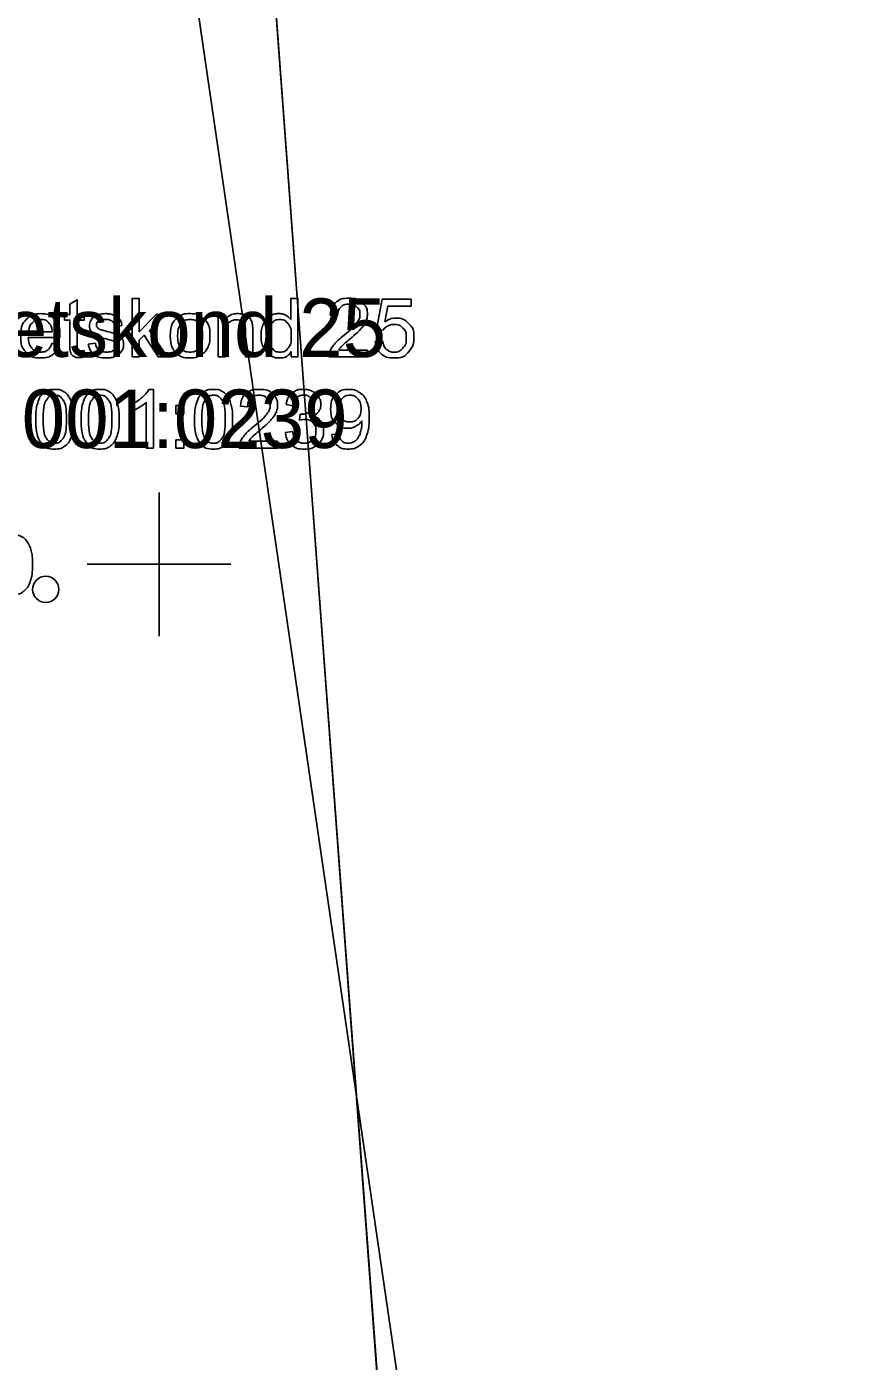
# Model space of a CAD drawing. Extents: x 700746 to 706058, y 6570320 to 6580460.
# Drawn here: x 703387.1 to 703467.1, y 6576222.3 to 6576352.4 of the extents above; entities that cross this region are included whole.
import ezdxf

# ---------------------------------------------------------------- set-up
doc = ezdxf.new("R2010")
doc.units = 0
for name, color, linetype in [('HALJASTUS', 7, 'Continuous'), ('Kaitsevöönd', 7, 'Continuous'), ('kataster', 7, 'Continuous'), ('Plokid', 7, 'Continuous'), ('VORK', 7, 'Continuous'), ('VWX2_MV_PLOKK', 7, 'Continuous')]:
    doc.layers.add(name, color=color, linetype=linetype)

msp = doc.modelspace()

# ---------------------------------------------------------------- linework, layer by layer
at = {"layer": 'HALJASTUS'}
msp.add_circle((703388.95, 6576297.55), 1.28, dxfattribs=at)
at = {"layer": 'Kaitsevöönd'}
msp.add_lwpolyline([(703341.02, 6576780.18), (703353.27, 6576691.8), (703361.05, 6576648.11), (703361.38, 6576646.79), (703378.43, 6576537.56), (703379.92, 6576517.69), (703382.07, 6576503.63), (703404.08, 6576352.03), (703454.73, 6576005.46)], dxfattribs=at)
at = {"layer": 'kataster'}
for points in [[(703391.3, 6576321.42), (703391.3, 6576323.8), (703390.78, 6576323.8), (703390.78, 6576324.34), (703391.3, 6576324.34), (703391.3, 6576325.36), (703392, 6576325.78), (703392, 6576324.34), (703392.7, 6576324.34), (703392.7, 6576323.8), (703392, 6576323.8), (703392, 6576321.38)], [(703397.37, 6576320.21), (703397.37, 6576325.91), (703398.07, 6576325.91), (703398.07, 6576322.66), (703399.73, 6576324.34), (703400.64, 6576324.34), (703399.06, 6576322.8), (703400.8, 6576320.21), (703399.93, 6576320.21), (703398.56, 6576322.32), (703398.07, 6576321.84), (703398.07, 6576320.21), (703397.37, 6576320.21)], [(703412.84, 6576323.86), (703412.84, 6576325.91), (703413.54, 6576325.91), (703413.54, 6576320.21), (703412.89, 6576320.21)], [(703421.86, 6576322.82), (703421.2, 6576322.9), (703421.76, 6576325.83), (703424.59, 6576325.83), (703424.59, 6576325.16), (703422.32, 6576325.16), (703422.01, 6576323.63)], [(703405.78, 6576320.21), (703405.78, 6576324.34), (703406.41, 6576324.34), (703406.41, 6576323.75)], [(703417.41, 6576324.21), (703416.69, 6576324.28)], [(703387.27, 6576322.67), (703389.58, 6576322.67)], [(703396.38, 6576323.27), (703395.7, 6576323.18)], [(703409.14, 6576322.75), (703409.14, 6576320.21), (703408.44, 6576320.21), (703408.44, 6576322.72)], [(703390.32, 6576322.09), (703387.23, 6576322.09)], [(703389.57, 6576321.54), (703390.3, 6576321.45)], [(703393.1, 6576321.44), (703393.79, 6576321.55)], [(703406.48, 6576322.46), (703406.48, 6576320.21), (703405.78, 6576320.21)], [(703421.08, 6576321.7), (703421.81, 6576321.76)], [(703392.7, 6576320.83), (703392.8, 6576320.21)], [(703412.89, 6576320.21), (703412.89, 6576320.73)], [(703420.33, 6576320.88), (703420.33, 6576320.21), (703416.56, 6576320.21)], [(703417.53, 6576320.88), (703420.33, 6576320.88)], [(703399, 6576317.05), (703399.45, 6576317.05), (703399.45, 6576311.33)], [(703397.36, 6576314.94), (703397.36, 6576315.62)], [(703399.45, 6576311.33), (703398.75, 6576311.33), (703398.75, 6576315.79)], [(703401.64, 6576314.67), (703401.64, 6576315.46), (703402.43, 6576315.46), (703402.43, 6576314.67), (703401.64, 6576314.67)], [(703408.65, 6576315.33), (703407.93, 6576315.41)], [(703413.09, 6576315.45), (703412.39, 6576315.57)], [(703413.7, 6576314.03), (703413.78, 6576314.64)], [(703412.32, 6576312.84), (703413.02, 6576312.93)], [(703416.85, 6576312.65), (703417.52, 6576312.71)], [(703401.64, 6576311.33), (703401.64, 6576312.12), (703402.43, 6576312.12), (703402.43, 6576311.33), (703401.64, 6576311.33)], [(703411.56, 6576312), (703411.56, 6576311.33), (703407.8, 6576311.33)], [(703408.77, 6576312), (703411.56, 6576312)]]:
    msp.add_lwpolyline(points, dxfattribs=at)
for points in [[(703416.56, 6576320.21), (703416.55, 6576320.46), (703416.64, 6576320.69), (703416.79, 6576321.08), (703417.1, 6576321.45), (703417.42, 6576321.83), (703418.02, 6576322.31), (703418.95, 6576323.08), (703419.27, 6576323.52), (703419.6, 6576323.97), (703419.6, 6576324.36), (703419.6, 6576324.78), (703419.3, 6576325.07), (703419, 6576325.35), (703418.53, 6576325.35), (703418.02, 6576325.35), (703417.72, 6576325.05), (703417.42, 6576324.74), (703417.41, 6576324.21)], [(703416.69, 6576324.28), (703416.76, 6576325.09), (703417.25, 6576325.51), (703417.73, 6576325.93), (703418.54, 6576325.93), (703419.36, 6576325.93), (703419.84, 6576325.47), (703420.32, 6576325.02), (703420.32, 6576324.35), (703420.32, 6576324.01), (703420.18, 6576323.67), (703420.04, 6576323.34), (703419.71, 6576322.98), (703419.39, 6576322.61), (703418.64, 6576321.98), (703418.01, 6576321.45), (703417.83, 6576321.26), (703417.65, 6576321.07), (703417.53, 6576320.88)], [(703390.3, 6576321.45), (703390.12, 6576320.82), (703389.66, 6576320.47), (703389.2, 6576320.12), (703388.48, 6576320.12), (703387.57, 6576320.12), (703387.04, 6576320.67), (703386.51, 6576321.23), (703386.51, 6576322.24), (703386.51, 6576323.28), (703387.05, 6576323.85), (703387.59, 6576324.43), (703388.44, 6576324.43), (703389.27, 6576324.43), (703389.79, 6576323.87), (703390.32, 6576323.3), (703390.32, 6576322.28), (703390.32, 6576322.22), (703390.32, 6576322.09)], [(703389.58, 6576322.67), (703389.53, 6576323.19), (703389.32, 6576323.45), (703388.98, 6576323.86), (703388.45, 6576323.86), (703387.97, 6576323.86), (703387.64, 6576323.53), (703387.31, 6576323.21), (703387.27, 6576322.67)], [(703395.7, 6576323.18), (703395.65, 6576323.5), (703395.43, 6576323.68), (703395.2, 6576323.86), (703394.79, 6576323.86), (703394.31, 6576323.86), (703394.11, 6576323.7), (703393.9, 6576323.54), (703393.9, 6576323.32), (703393.9, 6576323.19), (703393.98, 6576323.08), (703394.07, 6576322.96), (703394.25, 6576322.89), (703394.36, 6576322.85), (703394.87, 6576322.71), (703395.62, 6576322.51), (703395.91, 6576322.39), (703396.21, 6576322.26), (703396.37, 6576322.02), (703396.54, 6576321.78), (703396.54, 6576321.42), (703396.54, 6576321.07), (703396.34, 6576320.76), (703396.13, 6576320.45), (703395.75, 6576320.28), (703395.36, 6576320.12), (703394.87, 6576320.12), (703394.07, 6576320.12), (703393.64, 6576320.45), (703393.22, 6576320.78), (703393.1, 6576321.44)], [(703393.79, 6576321.55), (703393.85, 6576321.13), (703394.12, 6576320.91), (703394.39, 6576320.69), (703394.87, 6576320.69), (703395.35, 6576320.69), (703395.59, 6576320.89), (703395.82, 6576321.08), (703395.82, 6576321.35), (703395.82, 6576321.58), (703395.61, 6576321.72), (703395.47, 6576321.81), (703394.9, 6576321.96), (703394.12, 6576322.15), (703393.83, 6576322.29), (703393.53, 6576322.44), (703393.38, 6576322.69), (703393.22, 6576322.94), (703393.22, 6576323.24), (703393.22, 6576323.52), (703393.35, 6576323.75), (703393.47, 6576323.99), (703393.69, 6576324.14), (703393.86, 6576324.26), (703394.14, 6576324.35), (703394.42, 6576324.43), (703394.74, 6576324.43), (703395.23, 6576324.43), (703395.6, 6576324.29), (703395.97, 6576324.15), (703396.14, 6576323.91), (703396.32, 6576323.67), (703396.38, 6576323.27)], [(703401.09, 6576322.27), (703401.09, 6576323.42), (703401.73, 6576323.97), (703402.26, 6576324.43), (703403.03, 6576324.43), (703403.88, 6576324.43), (703404.42, 6576323.87), (703404.96, 6576323.31), (703404.96, 6576322.33), (703404.96, 6576321.53), (703404.72, 6576321.08), (703404.48, 6576320.62), (703404.03, 6576320.37), (703403.57, 6576320.12), (703403.03, 6576320.12), (703402.16, 6576320.12), (703401.63, 6576320.67), (703401.09, 6576321.23), (703401.09, 6576322.27)], [(703401.81, 6576322.27), (703401.81, 6576321.48), (703402.16, 6576321.08), (703402.51, 6576320.69), (703403.03, 6576320.69), (703403.55, 6576320.69), (703403.89, 6576321.09), (703404.24, 6576321.48), (703404.24, 6576322.3), (703404.24, 6576323.06), (703403.89, 6576323.46), (703403.54, 6576323.85), (703403.03, 6576323.85), (703402.51, 6576323.85), (703402.16, 6576323.46), (703401.81, 6576323.07), (703401.81, 6576322.27)], [(703406.41, 6576323.75), (703406.87, 6576324.43), (703407.72, 6576324.43), (703408.1, 6576324.43), (703408.41, 6576324.3), (703408.72, 6576324.16), (703408.88, 6576323.94), (703409.03, 6576323.73), (703409.1, 6576323.43), (703409.14, 6576323.23), (703409.14, 6576322.75)], [(703412.89, 6576320.73), (703412.5, 6576320.12), (703411.73, 6576320.12), (703411.24, 6576320.12), (703410.83, 6576320.39), (703410.41, 6576320.66), (703410.18, 6576321.15), (703409.96, 6576321.64), (703409.96, 6576322.27), (703409.96, 6576322.89), (703410.16, 6576323.39), (703410.37, 6576323.89), (703410.78, 6576324.16), (703411.19, 6576324.43), (703411.7, 6576324.43), (703412.07, 6576324.43), (703412.36, 6576324.27), (703412.65, 6576324.12), (703412.84, 6576323.86)], [(703410.68, 6576322.27), (703410.68, 6576321.48), (703411.01, 6576321.08), (703411.35, 6576320.69), (703411.8, 6576320.69), (703412.26, 6576320.69), (703412.58, 6576321.06), (703412.9, 6576321.44), (703412.9, 6576322.21), (703412.9, 6576323.06), (703412.58, 6576323.46), (703412.25, 6576323.85), (703411.77, 6576323.85), (703411.3, 6576323.85), (703410.99, 6576323.47), (703410.68, 6576323.09), (703410.68, 6576322.27)], [(703422.01, 6576323.63), (703422.52, 6576323.99), (703423.09, 6576323.99), (703423.83, 6576323.99), (703424.34, 6576323.47), (703424.86, 6576322.96), (703424.86, 6576322.14), (703424.86, 6576321.37), (703424.41, 6576320.8), (703423.86, 6576320.11), (703422.91, 6576320.11), (703422.13, 6576320.11), (703421.64, 6576320.55), (703421.15, 6576320.98), (703421.08, 6576321.7)], [(703408.44, 6576322.72), (703408.44, 6576323.15), (703408.35, 6576323.36), (703408.27, 6576323.57), (703408.06, 6576323.7), (703407.86, 6576323.82), (703407.58, 6576323.82), (703407.13, 6576323.82), (703406.81, 6576323.54), (703406.48, 6576323.25), (703406.48, 6576322.46)], [(703421.81, 6576321.76), (703421.89, 6576321.23), (703422.19, 6576320.96), (703422.49, 6576320.68), (703422.91, 6576320.68), (703423.42, 6576320.68), (703423.77, 6576321.07), (703424.12, 6576321.45), (703424.12, 6576322.08), (703424.12, 6576322.68), (703423.78, 6576323.03), (703423.45, 6576323.37), (703422.9, 6576323.37), (703422.56, 6576323.37), (703422.29, 6576323.22), (703422.02, 6576323.06), (703421.86, 6576322.82)], [(703387.23, 6576322.09), (703387.27, 6576321.41), (703387.62, 6576321.05), (703387.97, 6576320.69), (703388.48, 6576320.69), (703388.87, 6576320.69), (703389.14, 6576320.89), (703389.41, 6576321.1), (703389.57, 6576321.54)], [(703392.8, 6576320.21), (703392.5, 6576320.15), (703392.27, 6576320.15), (703391.89, 6576320.15), (703391.68, 6576320.27), (703391.47, 6576320.39), (703391.39, 6576320.59), (703391.3, 6576320.79), (703391.3, 6576321.42)], [(703392, 6576321.38), (703392, 6576321.08), (703392.04, 6576320.99), (703392.07, 6576320.9), (703392.16, 6576320.85), (703392.24, 6576320.8), (703392.39, 6576320.8), (703392.51, 6576320.8), (703392.7, 6576320.83)], [(703387.97, 6576314.14), (703387.97, 6576315.15), (703388.18, 6576315.77), (703388.38, 6576316.39), (703388.79, 6576316.72), (703389.2, 6576317.05), (703389.82, 6576317.05), (703390.28, 6576317.05), (703390.63, 6576316.87), (703390.98, 6576316.68), (703391.2, 6576316.33), (703391.43, 6576315.99), (703391.55, 6576315.49), (703391.68, 6576314.99), (703391.68, 6576314.14), (703391.68, 6576313.14), (703391.48, 6576312.52), (703391.27, 6576311.9), (703390.86, 6576311.57), (703390.45, 6576311.23), (703389.82, 6576311.23), (703389, 6576311.23), (703388.53, 6576311.82), (703387.97, 6576312.54), (703387.97, 6576314.14)], [(703388.69, 6576314.14), (703388.69, 6576312.73), (703389.02, 6576312.27), (703389.34, 6576311.81), (703389.82, 6576311.81), (703390.31, 6576311.81), (703390.63, 6576312.27), (703390.96, 6576312.74), (703390.96, 6576314.14), (703390.96, 6576315.55), (703390.63, 6576316.01), (703390.31, 6576316.47), (703389.82, 6576316.47), (703389.34, 6576316.47), (703389.05, 6576316.07), (703388.69, 6576315.54), (703388.69, 6576314.14)], [(703392.39, 6576314.14), (703392.39, 6576315.15), (703392.6, 6576315.77), (703392.81, 6576316.39), (703393.22, 6576316.72), (703393.63, 6576317.05), (703394.25, 6576317.05), (703394.71, 6576317.05), (703395.06, 6576316.87), (703395.4, 6576316.68), (703395.63, 6576316.33), (703395.85, 6576315.99), (703395.98, 6576315.49), (703396.11, 6576314.99), (703396.11, 6576314.14), (703396.11, 6576313.14), (703395.9, 6576312.52), (703395.7, 6576311.9), (703395.29, 6576311.57), (703394.88, 6576311.23), (703394.25, 6576311.23), (703393.43, 6576311.23), (703392.96, 6576311.82), (703392.39, 6576312.54), (703392.39, 6576314.14)], [(703393.12, 6576314.14), (703393.12, 6576312.73), (703393.44, 6576312.27), (703393.77, 6576311.81), (703394.25, 6576311.81), (703394.73, 6576311.81), (703395.06, 6576312.27), (703395.39, 6576312.74), (703395.39, 6576314.14), (703395.39, 6576315.55), (703395.06, 6576316.01), (703394.73, 6576316.47), (703394.24, 6576316.47), (703393.76, 6576316.47), (703393.48, 6576316.07), (703393.12, 6576315.54), (703393.12, 6576314.14)], [(703397.36, 6576315.62), (703397.94, 6576315.9), (703398.38, 6576316.29), (703398.82, 6576316.68), (703399, 6576317.05)], [(703403.46, 6576314.14), (703403.46, 6576315.15), (703403.67, 6576315.77), (703403.88, 6576316.39), (703404.29, 6576316.72), (703404.7, 6576317.05), (703405.32, 6576317.05), (703405.78, 6576317.05), (703406.12, 6576316.87), (703406.47, 6576316.68), (703406.69, 6576316.33), (703406.92, 6576315.99), (703407.05, 6576315.49), (703407.17, 6576314.99), (703407.17, 6576314.14), (703407.17, 6576313.14), (703406.97, 6576312.52), (703406.76, 6576311.9), (703406.35, 6576311.57), (703405.94, 6576311.23), (703405.32, 6576311.23), (703404.49, 6576311.23), (703404.02, 6576311.82), (703403.46, 6576312.54), (703403.46, 6576314.14)], [(703404.18, 6576314.14), (703404.18, 6576312.73), (703404.51, 6576312.27), (703404.84, 6576311.81), (703405.32, 6576311.81), (703405.8, 6576311.81), (703406.13, 6576312.27), (703406.45, 6576312.74), (703406.45, 6576314.14), (703406.45, 6576315.55), (703406.13, 6576316.01), (703405.8, 6576316.47), (703405.31, 6576316.47), (703404.83, 6576316.47), (703404.54, 6576316.07), (703404.18, 6576315.54), (703404.18, 6576314.14)], [(703407.8, 6576311.33), (703407.79, 6576311.58), (703407.88, 6576311.82), (703408.02, 6576312.2), (703408.34, 6576312.57), (703408.66, 6576312.95), (703409.25, 6576313.44), (703410.18, 6576314.2), (703410.51, 6576314.64), (703410.83, 6576315.09), (703410.83, 6576315.49), (703410.83, 6576315.9), (703410.54, 6576316.19), (703410.24, 6576316.47), (703409.76, 6576316.47), (703409.26, 6576316.47), (703408.95, 6576316.17), (703408.65, 6576315.87), (703408.65, 6576315.33)], [(703407.93, 6576315.41), (703408, 6576316.21), (703408.48, 6576316.63), (703408.96, 6576317.05), (703409.78, 6576317.05), (703410.6, 6576317.05), (703411.08, 6576316.6), (703411.55, 6576316.14), (703411.55, 6576315.47), (703411.55, 6576315.13), (703411.41, 6576314.8), (703411.27, 6576314.47), (703410.95, 6576314.1), (703410.63, 6576313.74), (703409.87, 6576313.1), (703409.24, 6576312.57), (703409.06, 6576312.38), (703408.89, 6576312.19), (703408.77, 6576312)], [(703412.39, 6576315.57), (703412.52, 6576316.28), (703412.97, 6576316.66), (703413.43, 6576317.05), (703414.1, 6576317.05), (703414.57, 6576317.05), (703414.96, 6576316.85), (703415.36, 6576316.65), (703415.56, 6576316.31), (703415.77, 6576315.96), (703415.77, 6576315.57), (703415.77, 6576315.2), (703415.57, 6576314.9), (703415.38, 6576314.6), (703414.99, 6576314.42), (703415.49, 6576314.3), (703415.77, 6576313.94), (703416.05, 6576313.57), (703416.05, 6576313.02), (703416.05, 6576312.27), (703415.51, 6576311.75), (703414.96, 6576311.23), (703414.13, 6576311.23), (703413.38, 6576311.23), (703412.88, 6576311.68), (703412.39, 6576312.13), (703412.32, 6576312.84)], [(703413.78, 6576314.64), (703413.85, 6576314.64), (703413.89, 6576314.64), (703414.34, 6576314.64), (703414.69, 6576314.87), (703415.05, 6576315.1), (703415.05, 6576315.59), (703415.05, 6576315.97), (703414.79, 6576316.23), (703414.53, 6576316.48), (703414.12, 6576316.48), (703413.71, 6576316.48), (703413.44, 6576316.22), (703413.17, 6576315.96), (703413.09, 6576315.45)], [(703417.52, 6576312.71), (703417.6, 6576312.24), (703417.85, 6576312.02), (703418.09, 6576311.81), (703418.46, 6576311.81), (703418.78, 6576311.81), (703419.03, 6576311.96), (703419.27, 6576312.1), (703419.43, 6576312.35), (703419.58, 6576312.6), (703419.69, 6576313.02), (703419.79, 6576313.44), (703419.79, 6576313.87), (703419.79, 6576313.92), (703419.79, 6576314.01), (703419.58, 6576313.68), (703419.21, 6576313.47), (703418.85, 6576313.26), (703418.43, 6576313.26), (703417.72, 6576313.26), (703417.23, 6576313.78), (703416.74, 6576314.29), (703416.74, 6576315.13), (703416.74, 6576315.99), (703417.25, 6576316.52), (703417.76, 6576317.05), (703418.53, 6576317.05), (703419.09, 6576317.05), (703419.55, 6576316.75), (703420.01, 6576316.45), (703420.25, 6576315.9), (703420.49, 6576315.35), (703420.49, 6576314.3), (703420.49, 6576313.2), (703420.25, 6576312.56), (703420.01, 6576311.91), (703419.54, 6576311.57), (703419.08, 6576311.23), (703418.45, 6576311.23), (703417.78, 6576311.23), (703417.35, 6576311.61), (703416.93, 6576311.98), (703416.85, 6576312.65)], [(703419.71, 6576315.16), (703419.71, 6576315.77), (703419.39, 6576316.12), (703419.07, 6576316.47), (703418.62, 6576316.47), (703418.15, 6576316.47), (703417.81, 6576316.09), (703417.46, 6576315.71), (703417.46, 6576315.11), (703417.46, 6576314.56), (703417.79, 6576314.22), (703418.12, 6576313.88), (703418.6, 6576313.88), (703419.08, 6576313.88), (703419.4, 6576314.22), (703419.71, 6576314.56), (703419.71, 6576315.16)], [(703398.75, 6576315.79), (703398.5, 6576315.55), (703398.09, 6576315.31), (703397.68, 6576315.07), (703397.36, 6576314.94)], [(703413.02, 6576312.93), (703413.14, 6576312.34), (703413.43, 6576312.07), (703413.72, 6576311.81), (703414.13, 6576311.81), (703414.63, 6576311.81), (703414.97, 6576312.15), (703415.31, 6576312.5), (703415.31, 6576313), (703415.31, 6576313.48), (703414.99, 6576313.8), (703414.68, 6576314.11), (703414.19, 6576314.11), (703413.99, 6576314.11), (703413.7, 6576314.03)]]:
    msp.add_open_spline(points, degree=3, dxfattribs=at)
at = {"layer": 'Plokid'}
msp.add_lwpolyline([(703294.02, 6575933.8), (703311.73, 6576015.89), (703324.97, 6576203.4), (703382.07, 6576503.63), (703406.89, 6576414.25), (703421.79, 6576214.16), (703443.8, 6575689.35), (703467.14, 6575602.46), (703308.25, 6575608.58), (703295.51, 6575829.03)], dxfattribs=at)
at = {"layer": 'VORK'}
for q in [(703400, 6576307), (703400, 6576307), (703393, 6576300), (703393, 6576300), (703407, 6576300), (703400, 6576293), (703407, 6576300), (703400, 6576293)]:
    msp.add_line((703400, 6576300), q, dxfattribs=at)
msp.add_open_spline([(703383.93, 6576299.96), (703383.93, 6576300.97), (703384.14, 6576301.59), (703384.35, 6576302.2), (703384.76, 6576302.54), (703385.17, 6576302.87), (703385.79, 6576302.87), (703386.25, 6576302.87), (703386.59, 6576302.69), (703386.94, 6576302.5), (703387.17, 6576302.15), (703387.39, 6576301.8), (703387.52, 6576301.31), (703387.65, 6576300.81), (703387.65, 6576299.96), (703387.65, 6576298.96), (703387.44, 6576298.34), (703387.23, 6576297.72), (703386.82, 6576297.39), (703386.41, 6576297.05), (703385.79, 6576297.05), (703384.97, 6576297.05), (703384.5, 6576297.64), (703383.93, 6576298.35), (703383.93, 6576299.96)], degree=3, dxfattribs=at)
at = {"layer": 'VWX2_MV_PLOKK'}
msp.add_lwpolyline([(703443.86, 6575689.39), (703467.13, 6575602.53), (703308.24, 6575608.65), (703295.44, 6575828.99), (703294.04, 6575933.77), (703311.73, 6576015.89), (703324.97, 6576203.33), (703382.07, 6576503.63), (703406.94, 6576414.24), (703421.77, 6576214.18)], close=True, dxfattribs=at)

# ---------------------------------------------------------------- texts
at = {"layer": 'kataster'}
for s, p in [('Ahtme metskond 25', (703354.36, 6576320.21)), ('22901:001:0239', (703363.29, 6576311.33))]:
    msp.add_text(s, height=5.7, dxfattribs=at).set_placement(p)

doc.saveas('drawing.dxf')
